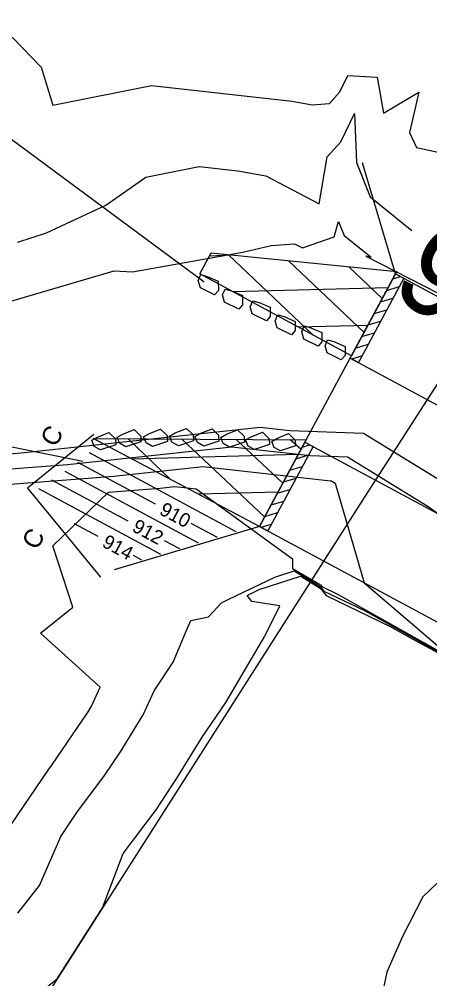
# Model space of a CAD drawing. Extents: x 1368651 to 1378602, y 762048 to 779328.
# Drawn here: x 1377164.1 to 1377208.5, y 762965.4 to 763069.1 of the extents above; entities that cross this region are included whole.
import ezdxf

# ---------------------------------------------------------------- set-up
doc = ezdxf.new("R2010")
doc.units = 0
for name, color, linetype in [('DTM Contours Major', 7, 'Continuous'), ('DTM Contours Major Text', 7, 'Continuous'), ('DTM Contours Minor', 7, 'Continuous'), ('Exist Plan Preparation Watershed Red', 7, 'Continuous'), ('Prop Erosion Rip Rap Class I Label', 7, 'Continuous'), ('Prop Erosion Rip Rap Single Stone CELL', 7, 'Continuous'), ('Prop Roadway Culvert', 7, 'Continuous'), ('Prop SS Cut Line', 7, 'Continuous'), ('Prop SS Cut Text', 7, 'Continuous'), ('Prop SS Misc', 7, 'Continuous')]:
    doc.layers.add(name, color=color, linetype=linetype)

msp = doc.modelspace()

# ---------------------------------------------------------------- linework, layer by layer
at = {"layer": 'DTM Contours Major'}
for points in [[(1377163.93, 763044.98), (1377167.03, 763045.98), (1377173.44, 763049), (1377177.76, 763052), (1377183.53, 763053.16), (1377187.72, 763052.68), (1377190.72, 763052.15), (1377196.51, 763049.14), (1377197.38, 763054.2), (1377198.84, 763055.83), (1377200.33, 763058.88), (1377200.54, 763053.6), (1377202.02, 763049.9), (1377206.53, 763046.25)], [(1377160.29, 763020.26), (1377169.31, 763020.95), (1377187.05, 763022.86), (1377195.53, 763021.93), (1377199.56, 763021.78), (1377208.17, 763016.5), (1377215.04, 763011.67)]]:
    msp.add_lwpolyline(points, dxfattribs=at)
at = {"layer": 'DTM Contours Minor'}
for points in [[(1377163.33, 763067.14), (1377166.46, 763063.88), (1377167.73, 763059.78), (1377178.39, 763061.92), (1377193.58, 763060.21), (1377195.76, 763059.82), (1377197.62, 763059.97), (1377198.75, 763061.23), (1377199.6, 763062.98), (1377202.76, 763062.81), (1377203.45, 763058.91), (1377207.27, 763061.18), (1377206.26, 763056.84), (1377207.02, 763055.22), (1377211.22, 763054.31)], [(1377163.16, 763038.61), (1377174.36, 763041.89), (1377176.31, 763041.78), (1377188.24, 763043.91), (1377191.32, 763044.62), (1377193.83, 763044.8), (1377194.7, 763044.39), (1377198.12, 763045.56), (1377198.61, 763047.22), (1377199.21, 763045.72), (1377202.12, 763043.36), (1377201.56, 763043.48), (1377224.92, 763031.51)], [(1377161.65, 763022.01), (1377164.3, 763022.21), (1377190.13, 763025), (1377193.34, 763024.64), (1377201.29, 763024.34), (1377218.28, 763013.93), (1377223.04, 763010.59), (1377225.75, 763009.77), (1377237.47, 763003.64), (1377238.96, 763002.13), (1377238.71, 763001.33), (1377242.47, 763000.6), (1377250.08, 762997.51), (1377254.58, 762994.6), (1377259.43, 762990.67), (1377262.56, 762987.4), (1377273.08, 762980.34), (1377274.85, 762977), (1377285.17, 762963.78)], [(1377158.93, 763018.5), (1377174.32, 763019.69), (1377183.98, 763020.73), (1377197.73, 763019.21), (1377197.83, 763019.21), (1377198.05, 763019.07), (1377198.23, 763018.95), (1377201.37, 763008.17), (1377210.57, 763000.31)], [(1377163.23, 762982.08), (1377167.2, 762987.92), (1377167.6, 762988.47), (1377171.53, 762994.25), (1377171.86, 762994.77), (1377172.82, 762996.89), (1377166.37, 763002.75), (1377169.86, 763005.55), (1377167.72, 763012.18), (1377173.73, 763017.99), (1377179.33, 763018.42), (1377180.9, 763018.59), (1377183.22, 763018.34), (1377193.62, 763010.78), (1377193.63, 763009.74), (1377196.12, 763008.28), (1377196.63, 763007.97), (1377196.79, 763007.77), (1377198.56, 763006.92), (1377212.36, 762999.17)], [(1377163.93, 762972.49), (1377166.26, 762975.46), (1377168.56, 762980.77), (1377170.31, 762983.35), (1377173.31, 762987.37), (1377175.04, 762989.92), (1377177.49, 762993.9), (1377178.68, 762996.51), (1377180.71, 762999.59), (1377182, 763002.71), (1377182.63, 763004.1), (1377184.54, 763004.49), (1377185.95, 763006.03), (1377186.65, 763006.37), (1377191.7, 763008.77), (1377193.81, 763009.47), (1377195.37, 763008.55), (1377196.61, 763007.79), (1377197.02, 763007.28), (1377201.41, 763005.18), (1377209.5, 763000.63)], [(1377163.24, 762961.47), (1377168.18, 762965.4), (1377173.08, 762973.06), (1377175.33, 762978.94), (1377178.87, 762983.63), (1377181.2, 762987.18), (1377183.86, 762991.51), (1377186.43, 762995.24), (1377190.64, 763002.43), (1377192.25, 763005.68), (1377189.23, 763006.15), (1377188.73, 763006.82), (1377189.16, 763007.03), (1377190.03, 763007.45), (1377194.47, 763008.91), (1377194.62, 763008.83), (1377196.6, 763007.61), (1377197.25, 763006.79), (1377204.25, 763003.43), (1377206.64, 763002.09), (1377214.92, 762997.61)], [(1377210.92, 762977.31), (1377207.72, 762974.24), (1377205.51, 762969.96), (1377203.82, 762966.09), (1377203.07, 762962.5)]]:
    msp.add_lwpolyline(points, dxfattribs=at)
at = {"layer": 'Exist Plan Preparation Watershed Red'}
msp.add_lwpolyline([(1373597.06, 767081.43), (1372938.47, 765818.8), (1372653.04, 765271.58), (1372900.45, 763223.22), (1372954.35, 762776.96), (1374508.77, 762195.85), (1375573.49, 762047.77), (1376441.31, 762392.26), (1376924.99, 762584.25), (1377201.49, 763017.52), (1377601.94, 763641.51), (1377736.1, 764021.28), (1377789.42, 764495.73), (1377827.52, 764834.78), (1378601.52, 765333.49), (1378471.1, 765535.9), (1378572.78, 766627.53)], dxfattribs=at)
at = {"layer": 'Prop Erosion Rip Rap Class I Label'}
for points in [[(1377184.06, 763040.65), (1377099.77, 763103.04), (1377105.23, 763113.17)], [(1377170.95, 763021.3), (1377019.59, 763051.83), (1377023.75, 763059.33)]]:
    msp.add_lwpolyline(points, dxfattribs=at)
at = {"layer": 'Prop Erosion Rip Rap Single Stone CELL'}
for p, q in [((1377183.62, 763041.55), (1377184.82, 763043.82)), ((1377184.66, 763043.52), (1377186.87, 763043.61)), ((1377184.82, 763043.82), (1377204.9, 763041.81)), ((1377195.81, 763034.98), (1377186.7, 763043.63)), ((1377201.35, 763035.23), (1377193.17, 763042.98)), ((1377203.33, 763038.89), (1377199.7, 763042.33)), ((1377200, 763032.72), (1377183.62, 763041.55)), ((1377204.9, 763041.81), (1377200, 763032.72)), ((1377187.15, 763039.64), (1377203.97, 763040.09)), ((1377194.23, 763035.83), (1377201.78, 763036.03)), ((1377172.09, 763023.76), (1377195.1, 763023.63)), ((1377190.06, 763014.28), (1377172.09, 763023.76)), ((1377180.45, 763019.35), (1377175.84, 763023.74)), ((1377190.61, 763015.3), (1377181.66, 763023.7)), ((1377192.57, 763018.95), (1377187.54, 763023.67)), ((1377195.1, 763023.63), (1377190.06, 763014.28)), ((1377194.54, 763022.59), (1377193.37, 763023.64)), ((1377194.25, 763022.05), (1377176.27, 763021.55)), ((1377192.05, 763017.97), (1377183.5, 763017.74))]:
    msp.add_line(p, q, dxfattribs=at)
for points in [[(1377183.72, 763041.48), (1377184.4, 763041.29), (1377185.6, 763040.77), (1377185.61, 763039.77), (1377185.19, 763039.3), (1377183.66, 763040.07), (1377183.44, 763040.83), (1377183.72, 763041.48)], [(1377186.34, 763039.92), (1377187.02, 763039.73), (1377188.22, 763039.22), (1377188.23, 763038.22), (1377187.81, 763037.75), (1377186.28, 763038.52), (1377186.06, 763039.28), (1377186.34, 763039.92)], [(1377189.32, 763038.66), (1377190.01, 763038.47), (1377191.21, 763037.95), (1377191.22, 763036.96), (1377190.8, 763036.49), (1377189.26, 763037.26), (1377189.04, 763038.01), (1377189.32, 763038.66)], [(1377192.03, 763037.13), (1377192.71, 763036.94), (1377193.91, 763036.43), (1377193.92, 763035.43), (1377193.5, 763034.96), (1377191.97, 763035.73), (1377191.75, 763036.49), (1377192.03, 763037.13)], [(1377194.9, 763035.93), (1377195.59, 763035.74), (1377196.79, 763035.22), (1377196.8, 763034.23), (1377196.38, 763033.76), (1377194.84, 763034.52), (1377194.62, 763035.28), (1377194.9, 763035.93)], [(1377197.42, 763034.43), (1377198.1, 763034.25), (1377199.3, 763033.73), (1377199.31, 763032.73), (1377198.89, 763032.26), (1377197.36, 763033.03), (1377197.14, 763033.79), (1377197.42, 763034.43)], [(1377174.67, 763023.9), (1377175.28, 763024.25), (1377176.5, 763024.73), (1377177.21, 763024.04), (1377177.24, 763023.41), (1377175.62, 763022.87), (1377174.93, 763023.25), (1377174.67, 763023.9)], [(1377177.53, 763023.95), (1377178.15, 763024.3), (1377179.36, 763024.78), (1377180.07, 763024.09), (1377180.1, 763023.46), (1377178.48, 763022.91), (1377177.79, 763023.29), (1377177.53, 763023.95)], [(1377180.33, 763024.02), (1377180.95, 763024.38), (1377182.17, 763024.86), (1377182.88, 763024.16), (1377182.91, 763023.53), (1377181.29, 763022.99), (1377180.59, 763023.37), (1377180.33, 763024.02)], [(1377183.08, 763023.99), (1377183.7, 763024.34), (1377184.92, 763024.83), (1377185.63, 763024.13), (1377185.66, 763023.5), (1377184.03, 763022.96), (1377183.34, 763023.34), (1377183.08, 763023.99)], [(1377185.86, 763023.88), (1377186.48, 763024.23), (1377187.69, 763024.71), (1377188.4, 763024.02), (1377188.43, 763023.39), (1377186.81, 763022.85), (1377186.12, 763023.23), (1377185.86, 763023.88)], [(1377171.93, 763023.58), (1377172.55, 763023.93), (1377173.76, 763024.41), (1377174.48, 763023.72), (1377174.51, 763023.08), (1377172.88, 763022.54), (1377172.19, 763022.92), (1377171.93, 763023.58)], [(1377188.54, 763023.61), (1377189.16, 763023.96), (1377190.38, 763024.44), (1377191.09, 763023.75), (1377191.12, 763023.11), (1377189.5, 763022.57), (1377188.81, 763022.95), (1377188.54, 763023.61)], [(1377191.37, 763023.46), (1377191.99, 763023.82), (1377193.2, 763024.3), (1377193.92, 763023.6), (1377193.95, 763022.97), (1377192.32, 763022.43), (1377191.63, 763022.81), (1377191.37, 763023.46)]]:
    msp.add_lwpolyline(points, dxfattribs=at)
at = {"layer": 'Prop Roadway Culvert'}
for p, q in [((1377204.76, 763041.56), (1377201.17, 763053.56)), ((1377190.06, 763014.28), (1377204.76, 763041.56)), ((1377204.47, 763041.02), (1377205.31, 763041.27)), ((1377204.76, 763041.56), (1377239.97, 763022.58)), ((1377203.8, 763039.77), (1377205.15, 763040.18)), ((1377203.13, 763038.53), (1377204.48, 763038.93)), ((1377202.46, 763037.28), (1377203.81, 763037.69)), ((1377201.79, 763036.04), (1377203.14, 763036.44)), ((1377201.12, 763034.79), (1377202.47, 763035.2)), ((1377200.44, 763033.55), (1377201.8, 763033.95)), ((1377199.86, 763032.47), (1377235.07, 763013.49)), ((1377200.03, 763032.38), (1377201.13, 763032.71)), ((1377194.67, 763022.83), (1377195.51, 763023.08)), ((1377194.96, 763023.38), (1377230.17, 763004.39)), ((1377194, 763021.59), (1377195.35, 763021.99)), ((1377193.32, 763020.34), (1377194.68, 763020.75)), ((1377192.65, 763019.1), (1377194.01, 763019.5)), ((1377191.98, 763017.85), (1377193.34, 763018.26)), ((1377191.31, 763016.61), (1377192.67, 763017.01)), ((1377190.64, 763015.36), (1377192, 763015.77)), ((1377190.06, 763014.28), (1377174.33, 763009.57)), ((1377190.06, 763014.28), (1377225.27, 762995.3)), ((1377190.22, 763014.19), (1377191.32, 763014.52))]:
    msp.add_line(p, q, dxfattribs=at)
for points in [[(1377200.74, 763031.99), (1377199.86, 763032.47), (1377204.76, 763041.56), (1377205.64, 763041.09)], [(1377190.94, 763013.81), (1377190.06, 763014.28), (1377194.96, 763023.38), (1377195.84, 763022.9)]]:
    msp.add_lwpolyline(points, close=True, dxfattribs=at)
at = {"layer": 'Prop SS Cut Line'}
for p, q in [((1377172.14, 763024.19), (1377164.97, 763018.42)), ((1377164.97, 763018.42), (1377172.88, 763008.8))]:
    msp.add_line(p, q, dxfattribs=at)
at = {"layer": 'Prop SS Misc'}
for p, q in [((1377187.54, 763013.67), (1377171.68, 763022.23)), ((1377178.81, 763016.67), (1377170.43, 763021.19)), ((1377183.46, 763012.45), (1377169.06, 763020.22)), ((1377175.87, 763014.84), (1377167.62, 763019.28)), ((1377179.39, 763011.23), (1377166.19, 763018.34)), ((1377172.62, 763013.17), (1377170.05, 763014.55)), ((1377185.5, 763013.06), (1377182.66, 763014.59)), ((1377181.43, 763011.84), (1377179.79, 763012.72)), ((1377177.35, 763010.62), (1377176.43, 763011.12))]:
    msp.add_line(p, q, dxfattribs=at)

# ---------------------------------------------------------------- texts
at = {"layer": 'DTM Contours Major Text'}
msp.add_text('910', height=10, rotation=324.6437, dxfattribs=at).set_placement((1377203.88, 763039.76))
at = {"layer": 'Prop SS Cut Text'}
for p in [(1377167.96, 763022.72), (1377165.96, 763011.61)]:
    msp.add_text('C', height=2, rotation=59.1802, dxfattribs=at).set_placement(p)
at = {"layer": 'Prop SS Misc'}
for s, p in [('910', (1377179.12, 763015.65)), ('912', (1377176.17, 763013.82)), ('914', (1377172.92, 763012.15))]:
    msp.add_text(s, height=1.505, rotation=331.6702, dxfattribs=at).set_placement(p)

doc.saveas('drawing.dxf')
